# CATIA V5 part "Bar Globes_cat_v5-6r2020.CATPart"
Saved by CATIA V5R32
Part number: Bar Globes
Bounding box of the stored display mesh (mm): x -5.91 to 5.91, y -4.926 to 5, z -5.992 to 5.992
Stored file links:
  D:\PROJECTS\Project 2022\CATIA V5 6R 2022\Resources\Tutorial Files\c13_catia_v5_6r2022_tut\c13tut2\Bench vice\Bar Globes_cat_v5-6r2020.CATPart
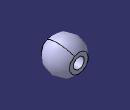
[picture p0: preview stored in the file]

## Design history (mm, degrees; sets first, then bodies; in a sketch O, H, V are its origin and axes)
Body1 (main body)
  Sketch1 on yz-plane, origin (0, 0, 0), H (0, 1, 0), V (0, 0, 1)
    arc A1 centre (0, 0) radius 6 from (6, 0) to (-6, 0) ccw
    line L1 (-6, 0) -> (6, 0)
    radius A1 = 6
    horizontal: L1 H
    coincidence: H L1
  Shaft1: profile Sketch1, axis edge of Sketch1, angle 360
  Sketch2 on yz-plane, origin (0, 0, 0), H (0, 1, 0), V (0, 0, 1)
    line L1 (-5, 7.2498) -> (5, 7.2498)
    line L2 (5, 7.2498) -> (5, -8.5554)
    line L3 (5, -8.5554) -> (1.27, -8.5554)
    line L4 (-5, -8.5554) -> (-5, 7.2498)
    line L5 (1.27, -8.5554) -> (1.27, -9.941)
    line L6 (1.27, -9.941) -> (8.2768, -9.941)
    line L7 (8.2768, -9.941) -> (8.2768, 9.8096)
    line L8 (8.2768, 9.8096) -> (-8.9775, 9.8096)
    line L9 (-8.9775, 9.8096) -> (-8.9775, -10.3789)
    line L10 (-8.9775, -10.3789) -> (-2.0145, -10.3789)
    line L11 (-2.0145, -10.3789) -> (-2.0145, -8.5554)
    point P12 (-2.0145, -8.5554)
    line L12 (-2.0145, -8.5554) -> (-5, -8.5554)
    length L1 = 10
    distance V L4 = 5
    horizontal: L1 H, L3 H, L6 H, L8 H, L10 H, L12 H
    vertical: L2 V, L4 V, L5 V, L7 V, L9 V, L11 V
    coincidence: P12 L3, L3 L12
  Pocket1: profile Sketch2, direction (-1, 0, 0), length 20, mirrored extent
  Sketch3 on face of Pocket1, origin (0.8583, -5, 1.5686), H (1, 0, 0), V (0, 0, 1)
    point P1 (-0.8583, -1.5686)
    reference intersected line E1 through (0, -1.5686) direction (-1, 0) from xy-plane
    reference intersected line E2 through (-0.8583, 0) direction (0, 1) from yz-plane
    coincidence: P1 E1, E2 P1
  Hole1: placed by Sketch3, at (0, -5, 0) direction (0, 1, 0), diameter 4, depth 10, countersink depth 1.5, countersink angle 90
